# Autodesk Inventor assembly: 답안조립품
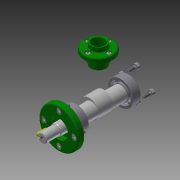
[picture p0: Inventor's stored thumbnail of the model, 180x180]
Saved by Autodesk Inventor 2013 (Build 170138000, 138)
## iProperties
Created: 2016-01
Part Number: 답안조립품
Document SubType Name: Assembly
Designer: User
Author: User
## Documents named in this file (11)
- C:\Users\User\Desktop\460126V1011\답안조립품.iam
- C:\Users\User\Desktop\460126V1011\본체.ipt
- C:\Users\User\Desktop\460126V1011\뒤커버.ipt
- C:\Users\User\Desktop\460126V1011\상부부시.ipt
- C:\Users\User\Desktop\460126V1011\앞커버.ipt
- C:\Users\User\Desktop\460126V1011\볼트 M4 x 10.ipt
- C:\Users\User\Desktop\460126V1011\볼트 M3 x 8.ipt
- C:\Users\User\Desktop\460126V1011\편심축.ipt
- C:\Users\User\Desktop\460126V1011\키 5 x 5 x 14.ipt
- C:\Users\User\Desktop\460126V1011\베어링 15 x 35 x 11.ipt
- C:\Users\User\Desktop\460126V1011\멈춤링 15 x 1.ipt
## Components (12 placed, 2 different names)
1. ISO 4762 M4 x 10:2
2. ISO 4762 M4 x 10:3
3. ISO 4762 M4 x 10:4
4. ISO 4762 M4 x 10:5
5. ISO 4762 M3 x 8:1
6. ISO 4762 M3 x 8:2
7. ISO 4762 M3 x 8:3
8. ISO 4762 M3 x 8:4
9. ISO 4762 M4 x 10:1
10. ISO 4762 M4 x 10:6
11. ISO 4762 M4 x 10:7
12. ISO 4762 M4 x 10:8
